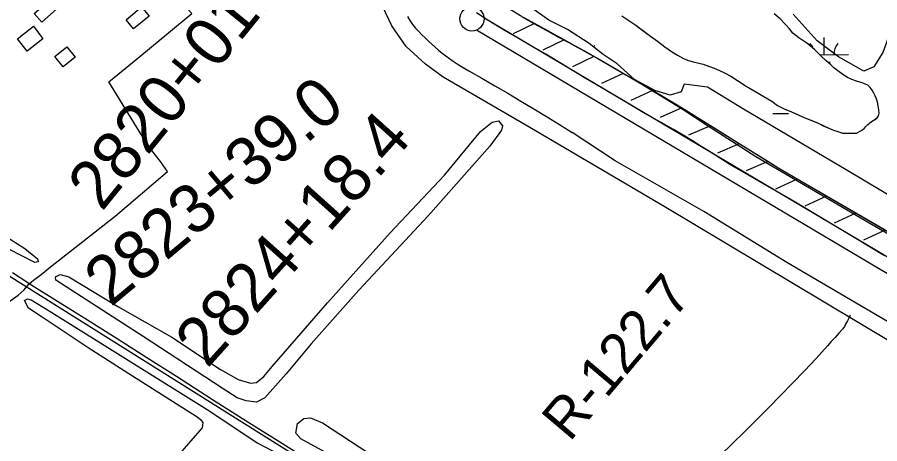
# Model space of a CAD drawing. Extents: x 3567028 to 3605064, y 510945 to 536587.
# Drawn here: x 3576780 to 3578560, y 527003 to 527882 of the extents above; entities that cross this region are included whole.
import ezdxf

# ---------------------------------------------------------------- set-up
doc = ezdxf.new("R2010")
doc.units = 0
for name, color, linetype in [('V-BLDG-OTLN', 7, 'Continuous'), ('V-DTCH-CNTR', 7, 'Continuous'), ('V-FLOD-BASE', 7, 'Continuous'), ('V-LEVE-TOET', 7, 'Continuous'), ('V-RAIL-TRAK', 7, 'Continuous'), ('V-RIVR-RANG-IDEN', 7, 'Continuous'), ('V-ROAD-CNTR', 7, 'Continuous'), ('V-RRAP-FSHR', 7, 'Continuous'), ('V-SITE-VEGE', 7, 'Continuous'), ('V-SURV-IDEN', 7, 'Continuous'), ('V-SURV-LINE', 7, 'Continuous'), ('V-TOPO-SHOR', 7, 'Continuous'), ('V-WETL-SWMP', 7, 'Continuous')]:
    doc.layers.add(name, color=color, linetype=linetype)

msp = doc.modelspace()

# ---------------------------------------------------------------- linework, layer by layer
at = {"layer": 'V-BLDG-OTLN'}
for points in [[(3576852.3, 527922.6), (3576867.7, 527904.6), (3576830.8, 527872.3), (3576815.2, 527890)], [(3577036.6, 527903.8), (3577052.4, 527884.5), (3577020.2, 527858.2), (3577005, 527876.8)], [(3576814.1, 527863.7), (3576833.4, 527838.2), (3576800.9, 527812.5), (3576781.1, 527837.7)], [(3576882.5, 527821.2), (3576899.6, 527800.3), (3576875.3, 527780.3), (3576858.1, 527801.1)]]:
    msp.add_lwpolyline(points, close=True, dxfattribs=at)
at = {"layer": 'V-DTCH-CNTR'}
for points in [[(3576969.2, 527749.2), (3577021.7, 527792.1), (3577140.3, 527889.8), (3577092, 527943.4), (3577159.7, 528004.7), (3577085.4, 528094.6), (3577139, 528138.6), (3577092.3, 528206.3), (3577291.1, 528358.8)], [(3576499.5, 527060.1), (3576671.3, 527212.8), (3576760.7, 527294.2), (3576782, 527309.2), (3576794, 527319.5), (3576805.2, 527332.4), (3576813.7, 527340), (3576830, 527352.2), (3576849.2, 527368), (3576982.3, 527472.4), (3577090.1, 527564.1), (3577075.8, 527584.6), (3577050.6, 527617.2), (3577015.3, 527674.4), (3576969.2, 527749.2)]]:
    msp.add_lwpolyline(points, dxfattribs=at)
at = {"layer": 'V-FLOD-BASE'}
for points in [[(3578250.3, 527578.8), (3578231.3, 527591.2), (3578212.1, 527603.4), (3578192.9, 527615.5), (3578173.5, 527627.3), (3578154, 527639.1), (3578134.5, 527650.6), (3578114.8, 527662), (3578095, 527673.2), (3578075.1, 527684.2), (3578034, 527708.3), (3577993, 527732.5), (3577952.2, 527757), (3577911.4, 527781.6), (3577870.8, 527806.4), (3577850, 527818), (3577829.3, 527829.7), (3577808.7, 527841.7), (3577788.2, 527853.8), (3577767.9, 527866.2), (3577747.7, 527878.7), (3577727.6, 527891.5)], [(3578569.4, 527390.1), (3578517.2, 527421.8), (3578479.4, 527444.7), (3578441.5, 527467.6), (3578403.5, 527490.2), (3578365.3, 527512.6), (3578327.1, 527534.8), (3578288.8, 527556.9), (3578250.3, 527578.8)]]:
    msp.add_lwpolyline(points, dxfattribs=at)
at = {"layer": 'V-LEVE-TOET'}
msp.add_line((3578014.2, 527586.6), (3577925, 527644.4), dxfattribs=at)
for points in [[(3577585.3, 527883.8), (3577590.6, 527875.4), (3577596, 527867.1), (3577602.2, 527860), (3577608.6, 527853.1), (3577615.1, 527846.3), (3577621.7, 527839.6), (3577628.5, 527833.1), (3577635.5, 527826.7), (3577642.5, 527820.5), (3577649.7, 527814.4), (3577657.1, 527808.5), (3577664.5, 527802.8), (3577672.1, 527797.2), (3577679.8, 527791.8), (3577687.7, 527786.6), (3577695.6, 527781.5), (3577703.7, 527776.6), (3577711.8, 527771.9), (3577738.8, 527756.6), (3577765.8, 527741.2), (3577792.6, 527725.5), (3577819.3, 527709.6), (3577845.9, 527693.6), (3577872.4, 527677.4), (3577898.8, 527661), (3577925, 527644.4)], [(3577820.7, 527883.8), (3577846, 527869.6), (3577871.4, 527855.5), (3577896.8, 527841.6), (3577922.4, 527827.9), (3577948, 527814.3), (3577977.9, 527797.4), (3578007.6, 527780.3), (3578037.2, 527763), (3578066.7, 527745.5), (3578096, 527727.7), (3578125.3, 527709.8), (3578154.4, 527691.8), (3578204.1, 527659.4), (3578253.9, 527627.3), (3578303.8, 527595.3)], [(3578731.1, 527164.2), (3578550.7, 527269.7), (3578367.8, 527376.5), (3578196.5, 527481.7), (3578014.2, 527586.6)], [(3578303.8, 527595.3), (3578459.8, 527504.2), (3578539.6, 527457.9), (3578619.3, 527411.4)]]:
    msp.add_lwpolyline(points, dxfattribs=at)
at = {"layer": 'V-RAIL-TRAK'}
msp.add_lwpolyline([(3577977.7, 526591.7), (3577950.8, 526608), (3577923.9, 526624.5), (3577897.2, 526641.1), (3577894.4, 526642.8), (3577870.5, 526657.9), (3577844, 526674.8), (3577817.5, 526692), (3577791.2, 526709.3), (3577765, 526726.7), (3577407.9, 526952.1), (3577332.9, 526999.1), (3577258.1, 527046.3), (3577183.4, 527093.7), (3577108.8, 527141.4), (3577047.7, 527180.2), (3576986.4, 527219), (3576925.1, 527257.6), (3576863.6, 527296), (3576805.2, 527332.4), (3576802.1, 527334.4), (3576770.5, 527355.1)], dxfattribs=at)
at = {"layer": 'V-ROAD-CNTR'}
for points in [[(3571107.5, 530923.8), (3571335.7, 530779.9), (3572456, 530074.7), (3572913.2, 529784.9), (3573353.2, 529506.1), (3574011.9, 529090.4), (3574465.9, 528803.8), (3574566.4, 528736.8), (3574909.2, 528519.1), (3575756.4, 527984.9), (3576622.6, 527437), (3577459.5, 526912.7), (3578223.7, 526427.4), (3578886.3, 526005.2), (3579395.2, 525684), (3580151.7, 525207.4), (3580699, 524864.7), (3581176, 524557.8)], [(3580788.2, 525782.1), (3580462.9, 526036.4), (3580289.2, 526162), (3580169.3, 526261.9), (3580060.2, 526334.7), (3579873.7, 526454.6), (3579591.6, 526617.3), (3579098.7, 526904), (3578578.5, 527215.4), (3578115.3, 527492.2), (3577829.6, 527660.1), (3577740.7, 527711.3), (3577658.9, 527759.1), (3577622.5, 527785.4), (3577582.8, 527822.2), (3577553, 527864.4), (3577527.7, 527919.3)], [(3578498.6, 527268), (3578496, 527262.1), (3578493.2, 527256.3), (3578490.1, 527250.6), (3578486.9, 527245), (3578483.4, 527239.6)], [(3578483.4, 527239.6), (3578475.4, 527231), (3578467.5, 527222.3), (3578459.8, 527213.5), (3578452.2, 527204.5), (3578428.3, 527178.8), (3578404.2, 527153.3), (3578380, 527128), (3578355.5, 527102.8), (3578331, 527077.8), (3578306.2, 527052.9), (3578281.3, 527028.2), (3578256.2, 527003.7), (3578231, 526979.3)]]:
    msp.add_lwpolyline(points, dxfattribs=at)
at = {"layer": 'V-RRAP-FSHR'}
for p, q in [((3577847.4, 527869.7), (3577803.5, 527848.4)), ((3577908.5, 527835.6), (3577864.6, 527814.3)), ((3577969.7, 527801.5), (3577925.7, 527780.2)), ((3578030.2, 527766.4), (3577985.9, 527746)), ((3578090.7, 527731.1), (3578046.3, 527710.7)), ((3578151.2, 527695.9), (3578106.8, 527675.4)), ((3578210.4, 527658.6), (3578165.5, 527639.5)), ((3578269.8, 527621.6), (3578224.9, 527602.4)), ((3578329.2, 527584.6), (3578284.3, 527565.4)), ((3578389.3, 527548.7), (3578345, 527528.2)), ((3578449.8, 527513.5), (3578405.5, 527493)), ((3578510.3, 527478.2), (3578466, 527457.8)), ((3578570.8, 527443), (3578526.5, 527422.6))]:
    msp.add_line(p, q, dxfattribs=at)
for points in [[(3577847.4, 527869.7), (3577818.9, 527885.6), (3577786.7, 527904.7)], [(3580594.9, 526196.3), (3580475.3, 526284.4), (3580386.2, 526356.2), (3580336, 526390), (3580284.2, 526429.6), (3580184.4, 526485.1), (3580064.7, 526557.1), (3579923.9, 526636.3), (3579763, 526746.2), (3579532.4, 526874.8), (3579336, 526992.4), (3579087.5, 527138), (3578853.3, 527277.4), (3578590.1, 527431.8), (3578351.8, 527570.5), (3578141.7, 527701.4), (3577976.3, 527797.9), (3577818.9, 527885.6)], [(3577908.5, 527835.6), (3577847.4, 527869.7)], [(3577969.7, 527801.5), (3577908.5, 527835.6)], [(3578030.2, 527766.4), (3577976.3, 527797.9), (3577969.7, 527801.5)], [(3578090.7, 527731.1), (3578030.2, 527766.4)], [(3578151, 527695.6), (3578141.7, 527701.4), (3578090.7, 527731.1)], [(3578210.4, 527658.6), (3578151, 527695.6)], [(3578269.8, 527621.6), (3578210.4, 527658.6)], [(3578329.2, 527584.6), (3578269.8, 527621.6)], [(3578389.3, 527548.7), (3578351.8, 527570.5), (3578329.2, 527584.6)], [(3578449.8, 527513.5), (3578389.3, 527548.7)], [(3578510.3, 527478.2), (3578449.8, 527513.5)], [(3578570.8, 527443), (3578510.3, 527478.2)]]:
    msp.add_lwpolyline(points, dxfattribs=at)
at = {"layer": 'V-SITE-VEGE'}
for p, q in [((3576795.1, 527298.5), (3576801.4, 527301.9)), ((3576801.4, 527301.9), (3576809, 527299.6)), ((3576803.9, 527282.3), (3576795.1, 527298.5)), ((3576809, 527299.6), (3576846.3, 527277.3)), ((3576832.1, 527263.6), (3576803.9, 527282.3)), ((3576846.3, 527277.3), (3577177.7, 527070.3)), ((3576926.6, 527200.5), (3576832.1, 527263.6)), ((3577018.4, 527142.3), (3576926.6, 527200.5)), ((3577149.6, 527059), (3577018.4, 527142.3)), ((3577177.7, 527070.3), (3577275.7, 527005)), ((3577160.6, 527051.1), (3577149.6, 527059)), ((3577148.2, 527019.2), (3577162.4, 527035.7)), ((3577164, 527046.8), (3577160.6, 527051.1)), ((3577162.4, 527035.7), (3577164, 527046.8)), ((3577089.7, 526952.5), (3577148.2, 527019.2)), ((3577275.7, 527005), (3577322.7, 526979.8))]:
    msp.add_line(p, q, dxfattribs=at)
for points in [[(3578597.9, 527916.6), (3578591, 527877.7), (3578566.1, 527809.8), (3578547.2, 527779.9), (3578527.2, 527770.9), (3578474.3, 527800.7), (3578430.4, 527833.6), (3578381.4, 527888.5)], [(3576695.1, 527469.6), (3576795.9, 527405.6), (3576822, 527384.2), (3576823.3, 527377.9), (3576817, 527376.6), (3576763.1, 527404.1)]]:
    msp.add_lwpolyline(points, dxfattribs=at)
for points in [[(3576860, 527339.9), (3576859.4, 527345.5), (3576860.9, 527347.6), (3576869.3, 527351.6), (3576886.7, 527347.1), (3576988.2, 527285.9), (3577099.5, 527222.5), (3577199.5, 527155.8), (3577236.1, 527135.6), (3577261.8, 527128.1), (3577273.7, 527129.3), (3577289.3, 527141.6), (3577306.4, 527162.2), (3577420.5, 527293.5), (3577549.4, 527437.8), (3577661.9, 527556.6), (3577736.1, 527646.7), (3577760.2, 527665.8), (3577773.5, 527669), (3577781.7, 527658.4), (3577779.4, 527649.4), (3577755.1, 527616.3), (3577628.2, 527472.7), (3577485.2, 527319.6), (3577386.8, 527209), (3577335.5, 527147.1), (3577291.3, 527097.6), (3577273.7, 527088.8), (3577252.8, 527091.3), (3577234, 527097.9), (3577203, 527117.3), (3577040.2, 527224.3)], [(3577878.9, 526701), (3577704.2, 526808.8), (3577472.3, 526954.7), (3577365.2, 527013.2), (3577354.9, 527024.5), (3577358.7, 527044.7), (3577371.5, 527055), (3577385.5, 527056.1), (3577410.4, 527045.9), (3577505.6, 526983.4), (3577724.4, 526841.3), (3577904.5, 526725.7), (3577910.7, 526720.7), (3577910.5, 526710.9), (3577900.5, 526697.8), (3577892, 526693.1)]]:
    msp.add_lwpolyline(points, close=True, dxfattribs=at)
at = {"layer": 'V-SURV-LINE'}
for points in [[(3577743.2, 527881.7), (3580271.6, 526383.4)], [(3580256.3, 526357.6), (3577727.9, 527855.9)]]:
    msp.add_lwpolyline(points, dxfattribs=at)
msp.add_circle((3577718.4, 527879), 25, dxfattribs=at)
at = {"layer": 'V-TOPO-SHOR'}
for points in [[(3578500.4, 527643.2), (3578511.6, 527643.6), (3578519.5, 527647.2), (3578524, 527650.3), (3578527.3, 527653.3), (3578530.9, 527656.8), (3578535.2, 527661), (3578538.9, 527664.3), (3578542.7, 527667.5), (3578550, 527671.4), (3578554.1, 527675), (3578555.7, 527676.9), (3578557, 527679.3), (3578558.2, 527684.6), (3578558, 527691.5), (3578556.4, 527699.9), (3578554.8, 527707.6), (3578553.3, 527714.1), (3578550.1, 527720.4), (3578547.8, 527725.7), (3578544.4, 527731.8), (3578539.9, 527737.5), (3578535.1, 527742), (3578523.3, 527747.1), (3578511.5, 527750.3), (3578502.1, 527753.8), (3578493.2, 527757.9), (3578483.6, 527764), (3578473.2, 527771.7), (3578465.3, 527778), (3578458.6, 527784.1), (3578448.4, 527793.5), (3578439.9, 527801.4), (3578433.4, 527807.7), (3578425.7, 527815.3), (3578415.9, 527824.2), (3578409.4, 527829.1), (3578401.1, 527834.4), (3578392.6, 527839.7), (3578380.4, 527849.7), (3578373.7, 527858.6), (3578364.9, 527868.4), (3578354.4, 527879.2), (3578342.2, 527889.2)], [(3578027.9, 527885.1), (3578042.4, 527875.6), (3578056.4, 527865.8), (3578071.4, 527854.6), (3578086.5, 527843.4), (3578101.3, 527832.8), (3578116.2, 527821.6), (3578130.2, 527811.8), (3578142.2, 527803.9), (3578154.6, 527797.6), (3578162.9, 527794.1), (3578174.7, 527790.6), (3578186.5, 527787.6), (3578195.4, 527785.6), (3578206.6, 527781.5), (3578218, 527777.2), (3578229.4, 527772.7), (3578239.4, 527768), (3578252.2, 527761.1), (3578266, 527752.1), (3578284.1, 527740.1), (3578336.9, 527709.6), (3578348.9, 527700.4), (3578362.8, 527693.7), (3578377.8, 527687.4), (3578393.2, 527680.3), (3578405.2, 527675.2), (3578416.4, 527670.7), (3578431.3, 527664.8), (3578444.1, 527658.2), (3578454.9, 527653.4), (3578464.4, 527649.7), (3578475, 527645.8), (3578483.3, 527643), (3578500.4, 527643.2)]]:
    msp.add_lwpolyline(points, dxfattribs=at)
at = {"layer": 'V-WETL-SWMP'}
for p, q in [((3577876.9, 527876.1), (3577841.5, 527901.8)), ((3578354.4, 527879.2), (3578342.2, 527889.2)), ((3577915.4, 527856.8), (3577876.9, 527876.1)), ((3578027.8, 527885.1), (3578042.4, 527875.6)), ((3578042.4, 527875.6), (3578056.4, 527865.8)), ((3578364.8, 527868.4), (3578354.4, 527879.2)), ((3577960.4, 527827.9), (3577915.4, 527856.8)), ((3578056.4, 527865.8), (3578086.5, 527843.4)), ((3578373.7, 527858.6), (3578364.8, 527868.4)), ((3578380.4, 527849.7), (3578373.7, 527858.6)), ((3578086.5, 527843.4), (3578101.2, 527832.8)), ((3578392.6, 527839.7), (3578380.4, 527849.7)), ((3578409.3, 527829.1), (3578392.6, 527839.7)), ((3578445.2, 527804.9), (3578444.9, 527840.9)), ((3577989.3, 527805.4), (3577960.4, 527827.9)), ((3578101.2, 527832.8), (3578116.2, 527821.6)), ((3578116.2, 527821.6), (3578130.2, 527811.8)), ((3578415.8, 527824.2), (3578409.3, 527829.1)), ((3578425.7, 527815.3), (3578415.8, 527824.2)), ((3578018.3, 527786.1), (3577989.3, 527805.4)), ((3578130.2, 527811.8), (3578142.2, 527803.9)), ((3578142.2, 527803.9), (3578154.6, 527797.6)), ((3578433.3, 527807.7), (3578425.7, 527815.3)), ((3578439.8, 527801.4), (3578433.3, 527807.7)), ((3578436.3, 527804.8), (3578495.2, 527805.3)), ((3578458.5, 527784.1), (3578439.8, 527801.4)), ((3578053.6, 527754), (3578018.3, 527786.1)), ((3578154.6, 527797.6), (3578162.8, 527794.1)), ((3578162.8, 527794.1), (3578174.7, 527790.5)), ((3578174.7, 527790.5), (3578186.5, 527787.6)), ((3578186.5, 527787.6), (3578195.3, 527785.6)), ((3578195.3, 527785.6), (3578217.9, 527777.2)), ((3578452.6, 527789.5), (3578457.3, 527789.6)), ((3578465.2, 527778), (3578458.5, 527784.1)), ((3578217.9, 527777.2), (3578229.4, 527772.7)), ((3578229.4, 527772.7), (3578239.4, 527768)), ((3578239.4, 527768), (3578252.2, 527761.1)), ((3578473.1, 527771.7), (3578465.2, 527778)), ((3578483.5, 527764), (3578473.1, 527771.7)), ((3578493.2, 527757.9), (3578483.5, 527764)), ((3578095.4, 527731.5), (3578053.6, 527754)), ((3578252.2, 527761.1), (3578284.1, 527740.1)), ((3578502, 527753.8), (3578493.2, 527757.9)), ((3578511.5, 527750.3), (3578502, 527753.8)), ((3578523.3, 527747.1), (3578511.5, 527750.3)), ((3578535.1, 527742), (3578523.3, 527747.1)), ((3578127.5, 527721.9), (3578095.4, 527731.5)), ((3578150, 527728.3), (3578127.5, 527721.9)), ((3578156.4, 527744.4), (3578150, 527728.3)), ((3578204.6, 527737.9), (3578156.4, 527744.4)), ((3578278.5, 527693), (3578204.6, 527737.9)), ((3578284.1, 527740.1), (3578336.8, 527709.6)), ((3578539.8, 527737.5), (3578535.1, 527742)), ((3578544.3, 527731.8), (3578539.8, 527737.5)), ((3578547.7, 527725.7), (3578544.3, 527731.8)), ((3578550.1, 527720.4), (3578547.7, 527725.7)), ((3578553.2, 527714.1), (3578550.1, 527720.4)), ((3578554.8, 527707.6), (3578553.2, 527714.1)), ((3578490.6, 527567.6), (3578278.5, 527693)), ((3578336.8, 527709.6), (3578348.8, 527700.4)), ((3578348.8, 527700.4), (3578362.8, 527693.7)), ((3578362.8, 527693.7), (3578377.8, 527687.4)), ((3578556.4, 527699.9), (3578554.8, 527707.6)), ((3578558, 527691.5), (3578556.4, 527699.9)), ((3578339.4, 527683.9), (3578371.4, 527684.2)), ((3578377.8, 527687.4), (3578393.1, 527680.3)), ((3578393.1, 527680.3), (3578405.1, 527675.2)), ((3578405.1, 527675.2), (3578431.3, 527664.8)), ((3578549.9, 527671.4), (3578554, 527674.9)), ((3578554, 527674.9), (3578555.6, 527676.9)), ((3578555.6, 527676.9), (3578557, 527679.3)), ((3578557, 527679.3), (3578558.2, 527684.6)), ((3578558.2, 527684.6), (3578558, 527691.5)), ((3578431.3, 527664.8), (3578444.1, 527658.1)), ((3578444.1, 527658.1), (3578454.9, 527653.4)), ((3578530.8, 527656.8), (3578535.2, 527661)), ((3578535.2, 527661), (3578538.9, 527664.3)), ((3578538.9, 527664.3), (3578542.6, 527667.5)), ((3578542.6, 527667.5), (3578549.9, 527671.4)), ((3578454.9, 527653.4), (3578464.3, 527649.7)), ((3578464.3, 527649.7), (3578475, 527645.8)), ((3578475, 527645.8), (3578483.2, 527643)), ((3578483.2, 527643), (3578500.3, 527643.2)), ((3578500.3, 527643.2), (3578511.6, 527643.6)), ((3578511.6, 527643.6), (3578519.4, 527647.2)), ((3578519.4, 527647.2), (3578524, 527650.3)), ((3578524, 527650.3), (3578527.3, 527653.3)), ((3578527.3, 527653.3), (3578530.8, 527656.8)), ((3578863.3, 527345.9), (3578490.6, 527567.6))]:
    msp.add_line(p, q, dxfattribs=at)
for centre, start, end in [((3577998.6, 527801.6), 139.7115, 146.4289), ((3578390, 527804.9), 21.7935, 41.2552), ((3578500.4, 527805.8), 139.7115, 181.2552)]:
    msp.add_arc(centre, 35.2, start, end, dxfattribs=at)

# ---------------------------------------------------------------- texts
at = {"layer": 'V-RIVR-RANG-IDEN'}
msp.add_text('R-122.7', height=83, rotation=49.7727, dxfattribs=at).set_placement((3577920, 527005.1))
at = {"layer": 'V-SURV-IDEN'}
for s, rotation, p in [('2820+01.4', 50.9258, (3576955, 527480)), ('2823+39.0', 39.8667, (3576973, 527283.4)), ('2824+18.4', 48.0753, (3577172.5, 527156.8))]:
    msp.add_text(s, height=100, rotation=rotation, dxfattribs=at).set_placement(p)

doc.saveas('drawing.dxf')
